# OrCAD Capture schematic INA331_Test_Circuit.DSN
size A; title: Low-Power, Single-Supply, CMOS INSTRUMENTATION; rev: 1.1; note: Datasheet : SBOS215C EVM : NA
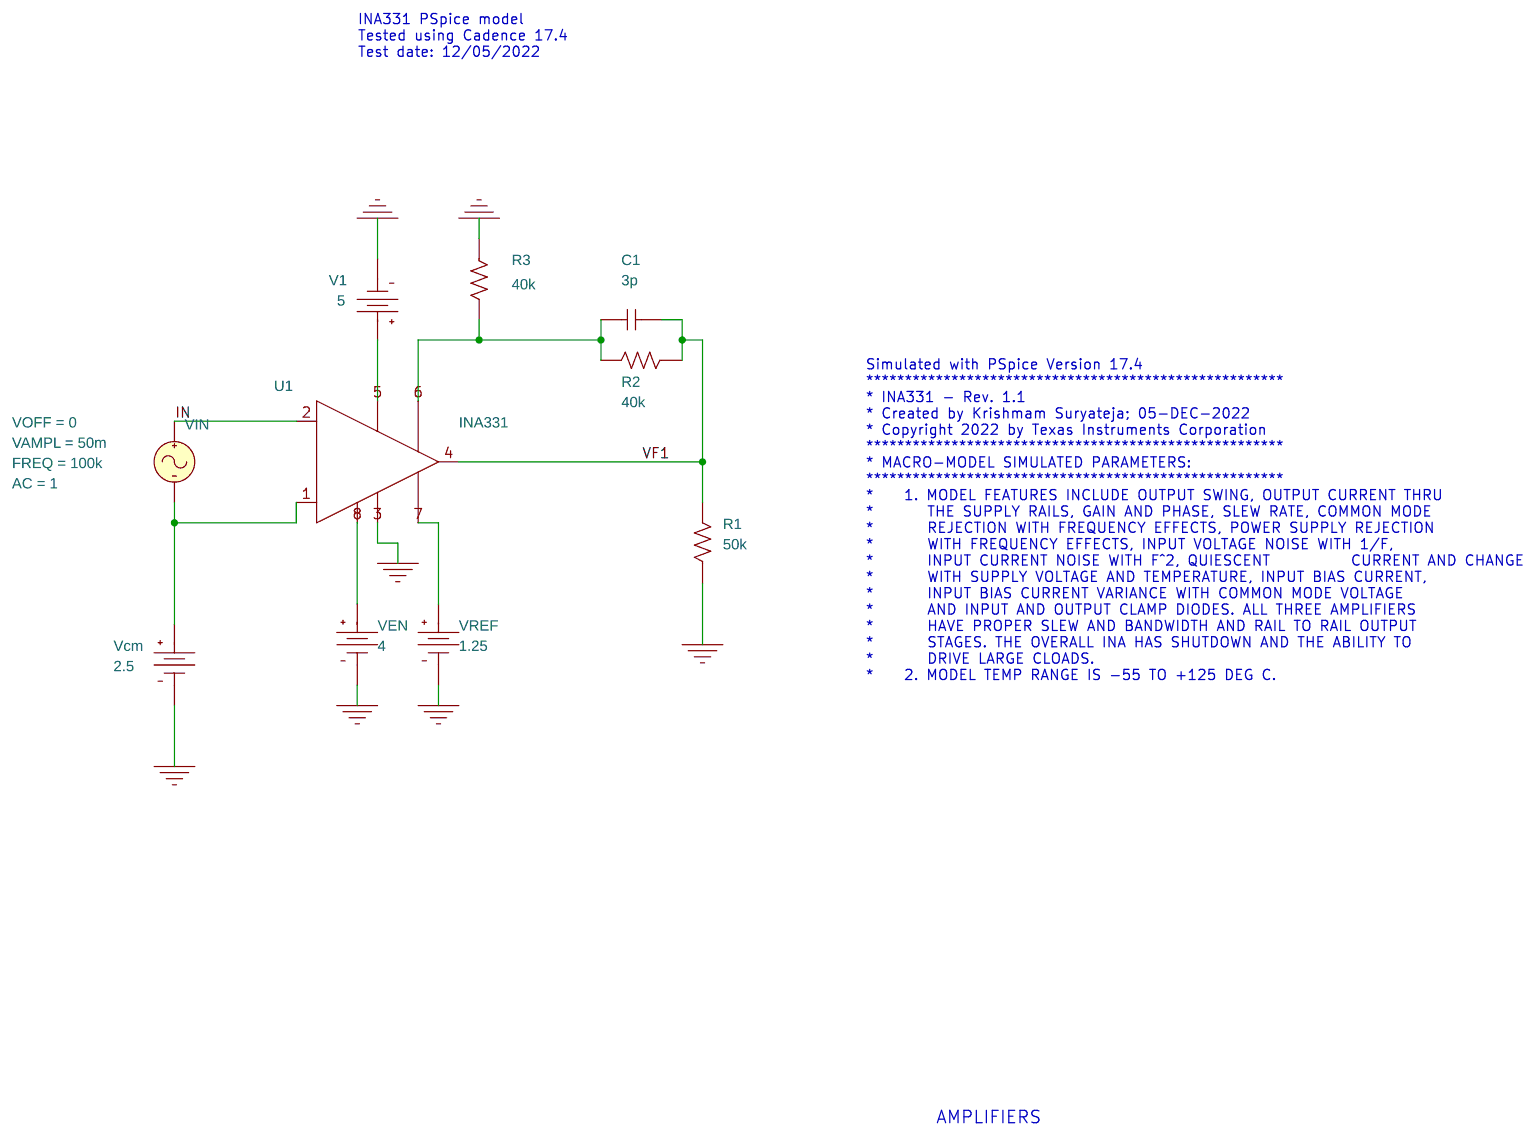
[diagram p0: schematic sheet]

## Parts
C1  3p  [RAD/CK05]
R1  50k  [AX/RC05]
R2  40k  [AX/RC05]
R3  40k  [AX/RC05]
U1  INA331
V1  VDC
Vcm  VDC
VEN  VDC
VIN  VSIN
VREF  VDC

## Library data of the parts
C1 = C
R1-R3 = R
U1 = INA331
V1 = VDC: DC: 5
Vcm = VDC: DC: 2.5
VEN = VDC: DC: 4
VIN = VSIN: AC: 1; FREQ: 100k; VAMPL: 50m; VOFF: 0
VREF = VDC: DC: 1.25

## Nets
0: R1.1 R3.1 U1.3(V-) V1.1(-) Vcm.1(-) VEN.1(-) VREF.1(-)
IN: U1.2(-) VIN.1(+)
VF1: C1.2 R1.2 R2.1 U1.4(OUT)
N14293709: C1.1 R2.2 R3.2 U1.6(RG)
N14293725: U1.5(V+) V1.0(+)
N14293915: U1.1(+) Vcm.0(+) VIN.2(-)
N14293935: U1.8(EN) VEN.0(+)
N14293947: U1.7(REF) VREF.0(+)

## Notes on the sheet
- INA331 PSpice model
  Tested using Cadence 17.4
  Test date: 12/05/2022
- Simulated with PSpice Version 17.4
  ******************************************************
  * INA331 - Rev. 1.1
  * Created by Krishmam Suryateja; 05-DEC-2022
  * Copyright 2022 by Texas Instruments Corporation
  ******************************************************
  * MACRO-MODEL SIMULATED PARAMETERS:
  ******************************************************
  *	1. MODEL FEATURES INCLUDE OUTPUT SWING, OUTPUT CURRENT THRU
  *	   THE SUPPLY RAILS, GAIN AND PHASE, SLEW RATE, COMMON MODE
  *	   REJECTION WITH FREQUENCY EFFECTS, POWER SUPPLY REJECTION
  *	   WITH FREQUENCY EFFECTS, INPUT VOLTAGE NOISE WITH 1/F,
  *	   INPUT CURRENT NOISE WITH F^2, QUIESCENT	CURRENT AND CHANGE
  *	   WITH SUPPLY VOLTAGE AND TEMPERATURE, INPUT BIAS CURRENT,
  *	   INPUT BIAS CURRENT VARIANCE WITH COMMON MODE VOLTAGE
  *	   AND INPUT AND OUTPUT CLAMP DIODES. ALL THREE AMPLIFIERS
  *	   HAVE PROPER SLEW AND BANDWIDTH AND RAIL TO RAIL OUTPUT
  *	   STAGES. THE OVERALL INA HAS SHUTDOWN AND THE ABILITY TO
  *	   DRIVE LARGE CLOADS.
  *	2. MODEL TEMP RANGE IS -55 TO +125 DEG C.
- AMPLIFIERS
